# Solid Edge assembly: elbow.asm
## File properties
Author: nakano
Template: iso metric assembly.asm
Last saved by: nakano
Revision: 17
Application: Solid Edge
Username: nakano
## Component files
asb-201.par
hitec hs-755hb.par
asb-06.par
hub-08.par
at-03.par
asb-04.par
hitec hs-645mg.par
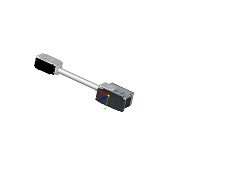
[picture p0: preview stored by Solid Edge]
